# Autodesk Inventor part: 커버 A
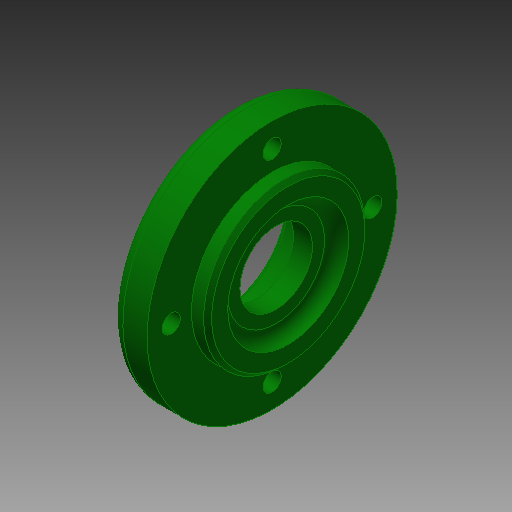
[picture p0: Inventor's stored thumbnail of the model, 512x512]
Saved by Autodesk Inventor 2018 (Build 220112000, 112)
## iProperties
Created: 2019-01
Part Number: 커버 A
Material: 알루미늄 6061
Document SubType Name: Modeling
Designer: mduedu
Density: 2.71 g/cm^3
Appearance: 진녹색
Mass: 67.6006 g
Surface Area: 94.463 cm^2
Volume: 24.9449 cm^3
Author: mduedu
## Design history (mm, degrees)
sketch "스케치1"
  geometry: L1 (0, 0)-(9, 0); L2 (9, 0)-(9, 31); L3 (9, 31)-(0, 31); L4 (0, 31)-(0, 0); L5 (9, 0)-(13, 0); L6 (13, 0)-(13, 20); L7 (13, 20)-(9, 20); L8 (9, 20)-(9, 0)
  constraints: 16 end point, 4 parallel, 2 horizontal, 2 perpendicular
  dimensions: "d0" = 13 distance between parallel lines of L6 L4; "d2" = 62 diameter of L3 L1; "d3" = 40 diameter of L7 L5; "d4" = 4 distance between parallel lines of L6 L2
revolve "회전1" sketch "스케치1" stored, may be unused: angle "d5" = 90 deg
sketch "스케치5"
  geometry: C1 r 19 at (0, 0); 1 further point
  constraints: 1 centre point, 1 coincident
  dimensions: "d34" = 38 diameter of C1
extrude "돌출1" join sketch "스케치5" distance "d35" = 3; taper "d36" = 0 deg
sketch "스케치2"
  geometry: L1 (9, -20)-(9, -31) reference; L2 (9, -31)-(0, -31) reference; L3 (0, -31)-(0, -19) reference; L4 (0, -19)-(-3, -19) reference; L5 (-3, -19)-(-3, 19) reference; L6 (-3, 19)-(0, 19) reference; L7 (0, 19)-(0, 31) reference; L8 (0, 31)-(9, 31) reference; L9 (9, 31)-(9, 20) reference; L10 (9, 20)-(13, 20) reference; L11 (13, 20)-(13, -20) reference; L12 (13, -20)-(9, -20) reference; L13 (-3, 0)-(5.3, 0); L14 (5.3, 0)-(5.3, 15); L15 (5.3, 15)-(-3, 15); L16 (-3, 15)-(-3, 0); L17 (5.3, 0)-(10, 0); L18 (10, 0)-(10, 9); L19 (10, 9)-(5.3, 9); L20 (5.3, 9)-(5.3, 0); L21 (10, 0)-(13, 0); L22 (13, 0)-(13, 15); L23 (13, 15)-(10, 15); L24 (10, 15)-(10, 0)
  constraints: 24 end point, 6 parallel, 3 horizontal, 3 perpendicular, 1 midpoint, 1 point on line
  dimensions: "d38" = 30 diameter of L15 L13; "d40" = 30 diameter of L23 L21; "d41" = 3 distance of L22.end L23.end; "d42" = 8.3 distance of L14.end L15.end; "d43" = 18 diameter of L19 L17
revolve "회전2" sketch "스케치2" stored, may be unused: angle "d12" = 90 deg
chamfer "모따기1" distance "d13" = 0.8; stored, may be unused: second distance "d14" = 2, angle "d15" = 30 deg
fillet "모깎기1" dims "d16" = 0.5
fillet "모깎기2" dims "d17" = 3
fillet "모깎기3" dims "d18" = 3
chamfer "모따기2" distance "d24" = 1; stored, may be unused: second distance "d25" = 2, angle "d26" = 45 deg
sketch "스케치3" dims "d19" = 50
  geometry: 6 further points
  constraints: 2 vertical alignment, 1 coincident, 7 other
  dimensions: "d22" = 360 deg dimension on point (0, 0) point (0, 25) (derived)
sketch "스케치4"
  geometry: 4 further points
  constraints: 4 other
hole "구멍1" sketch "스케치4" at (-25, 0), (0, -25), (25, 0), (0, 25) diameter "d27" = 4.5; stored, may be unused: countersink angle "d31" = 90 deg, drill point angle "d33" = 0 deg; dims "d28" = 6, "d29" = 8, "d30" = 4.6, "d32" = 8
fillet "모깎기6" dims "d47" = 1
node "솔리드1"
node "절단 모서리 투영2"
